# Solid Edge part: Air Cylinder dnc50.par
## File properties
Author: davee
Template: Normal.par
Last saved by: davee
Revision: 1
Application: Solid Edge
Accuracy: 0.990
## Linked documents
DNC-50-100 Cylinder.par
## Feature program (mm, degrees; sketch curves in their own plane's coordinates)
part copy "CopiedPart_1"
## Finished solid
Body 1: solid body, 27 faces, 44 edges, 20 vertices.
  Faces by surface: plane 16, cylinder 7, cone 4
  Edges by curve: line 30, circle 14
Bounding box of the edges (mm): 65.000 x 65.000 x 274.400, from (-32.5, -32.5, -66.4) to (32.5, 32.5, 208).
Cylindrical faces by radius (mm): R3.3235 x4, R8 x2, R20 x1
Conical faces (half-angle, radius in mm at the cone's reference point): 59 deg R3.3235 x4
Planar faces by outward normal: +x 2, +y 1, +z 2, -x 2, -y 1, -z 4, oblique 4
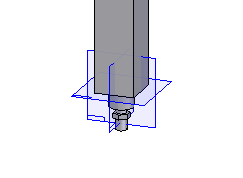
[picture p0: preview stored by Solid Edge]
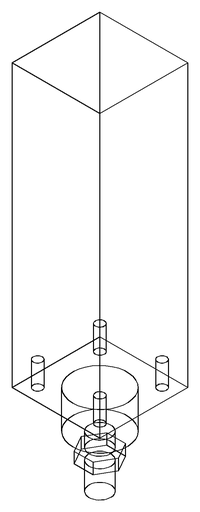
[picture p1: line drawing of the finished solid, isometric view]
